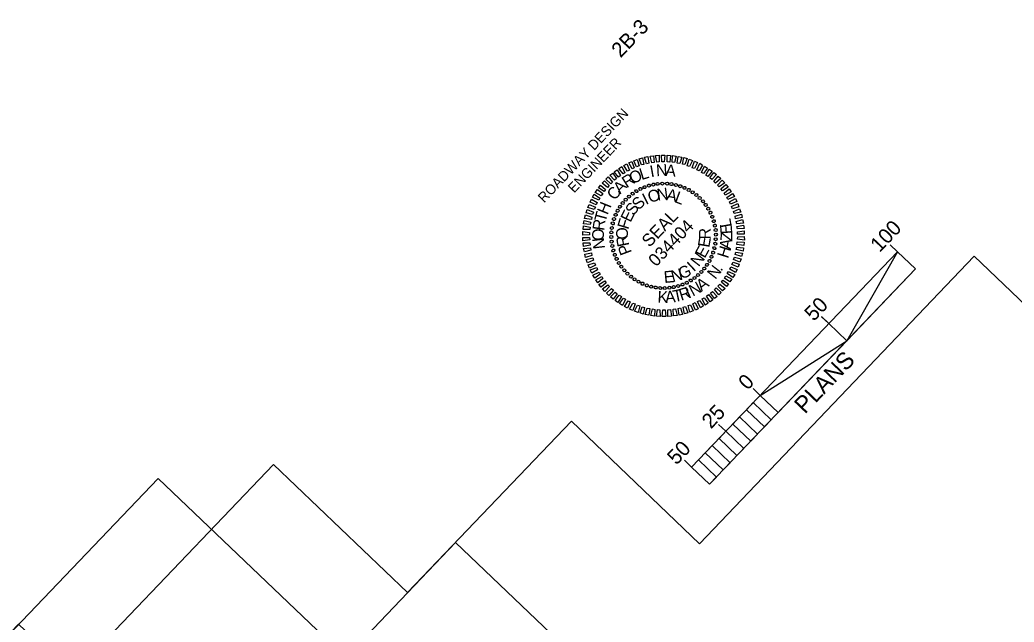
# Model space of a CAD drawing. Extents: x 2326836 to 2328631, y 602012 to 603789.
# Drawn here: x 2327551 to 2328051, y 603486 to 603789 of the extents above; entities that cross this region are included whole.
import ezdxf

# ---------------------------------------------------------------- set-up
doc = ezdxf.new("R2010")
doc.units = 0
for name, color, linetype in [('Scratch_Level_1', 7, 'Continuous'), ('Sheet Data Field CELL', 7, 'Continuous'), ('Sheet Plan CELL', 7, 'Continuous'), ('Sheet Title CELL', 7, 'Continuous')]:
    doc.layers.add(name, color=color, linetype=linetype)

msp = doc.modelspace()

# ---------------------------------------------------------------- linework, layer by layer
at = {"layer": 'Scratch_Level_1'}
msp.add_lwpolyline([(2326885.09, 602788.9), (2327620.52, 603558.61), (2327714.85, 603468.48), (2327770.17, 603526.38), (2328049.95, 603259.07), (2327259.2, 602431.46)], close=True, dxfattribs=at)
at = {"layer": 'Sheet Data Field CELL'}
for p, q in [((2327865.2, 603705.2), (2327865.2, 603705.2)), ((2327867.36, 603705.99), (2327867.36, 603705.99)), ((2327869.6, 603706.49), (2327869.6, 603706.49)), ((2327871.89, 603706.88), (2327871.89, 603706.88)), ((2327874.15, 603707.01), (2327874.15, 603707.01)), ((2327876.49, 603706.99), (2327876.49, 603706.99)), ((2327878.73, 603706.71), (2327878.73, 603706.71)), ((2327881.01, 603706.24), (2327881.01, 603706.24)), ((2327883.23, 603705.63), (2327883.23, 603705.63)), ((2327885.34, 603704.82), (2327885.34, 603704.82)), ((2327857.41, 603700.47), (2327857.41, 603700.47)), ((2327859.21, 603701.88), (2327859.21, 603701.88)), ((2327861.05, 603703.17), (2327861.05, 603703.17)), ((2327863.08, 603704.3), (2327863.08, 603704.3)), ((2327887.38, 603703.79), (2327887.38, 603703.79)), ((2327889.37, 603702.53), (2327889.37, 603702.53)), ((2327891.24, 603701.23), (2327891.24, 603701.23)), ((2327892.97, 603699.71), (2327892.97, 603699.71)), ((2327852.9, 603695.27), (2327852.9, 603695.27)), ((2327854.2, 603697.14), (2327854.2, 603697.14)), ((2327855.73, 603698.88), (2327855.73, 603698.88)), ((2327894.56, 603698.03), (2327894.56, 603698.03)), ((2327895.97, 603696.23), (2327895.97, 603696.23)), ((2327897.27, 603694.38), (2327897.27, 603694.38)), ((2327850.61, 603691.24), (2327850.61, 603691.24)), ((2327851.64, 603693.29), (2327851.64, 603693.29)), ((2327898.39, 603692.35), (2327898.39, 603692.35)), ((2327899.29, 603690.23), (2327899.29, 603690.23)), ((2327848.72, 603684.63), (2327848.72, 603684.63)), ((2327849.19, 603686.92), (2327849.19, 603686.92)), ((2327849.81, 603689.13), (2327849.81, 603689.13)), ((2327900.08, 603688.07), (2327900.08, 603688.07)), ((2327900.58, 603685.83), (2327900.58, 603685.83)), ((2327848.43, 603680.06), (2327848.43, 603680.06)), ((2327848.44, 603682.4), (2327848.44, 603682.4)), ((2327900.97, 603683.54), (2327900.97, 603683.54)), ((2327901.1, 603681.28), (2327901.1, 603681.28)), ((2327848.55, 603677.8), (2327848.55, 603677.8)), ((2327848.94, 603675.51), (2327848.94, 603675.51)), ((2327900.34, 603674.42), (2327900.34, 603674.42)), ((2327900.8, 603676.7), (2327900.8, 603676.7)), ((2327901.08, 603678.94), (2327901.08, 603678.94)), ((2327849.44, 603673.26), (2327849.44, 603673.26)), ((2327850.23, 603671.11), (2327850.23, 603671.11)), ((2327898.91, 603670.09), (2327898.91, 603670.09)), ((2327899.72, 603672.21), (2327899.72, 603672.21)), ((2327851.14, 603668.99), (2327851.14, 603668.99)), ((2327852.26, 603666.95), (2327852.26, 603666.95)), ((2327853.56, 603665.11), (2327853.56, 603665.11)), ((2327896.62, 603666.07), (2327896.62, 603666.07)), ((2327897.88, 603668.05), (2327897.88, 603668.05)), ((2327854.97, 603663.31), (2327854.97, 603663.31)), ((2327856.56, 603661.63), (2327856.56, 603661.63)), ((2327858.29, 603660.11), (2327858.29, 603660.11)), ((2327890.32, 603659.46), (2327890.32, 603659.46)), ((2327892.12, 603660.87), (2327892.12, 603660.87)), ((2327893.8, 603662.46), (2327893.8, 603662.46)), ((2327895.33, 603664.19), (2327895.33, 603664.19)), ((2327860.16, 603658.81), (2327860.16, 603658.81)), ((2327862.14, 603657.55), (2327862.14, 603657.55)), ((2327864.19, 603656.52), (2327864.19, 603656.52)), ((2327866.3, 603655.71), (2327866.3, 603655.71)), ((2327868.51, 603655.1), (2327868.51, 603655.1)), ((2327870.8, 603654.63), (2327870.8, 603654.63)), ((2327873.04, 603654.35), (2327873.04, 603654.35)), ((2327875.38, 603654.33), (2327875.38, 603654.33)), ((2327877.64, 603654.46), (2327877.64, 603654.46)), ((2327879.92, 603654.85), (2327879.92, 603654.85)), ((2327882.17, 603655.35), (2327882.17, 603655.35)), ((2327884.33, 603656.14), (2327884.33, 603656.14)), ((2327886.44, 603657.04), (2327886.44, 603657.04)), ((2327888.48, 603658.16), (2327888.48, 603658.16)), ((2327957.91, 603636.55), (2327954.3, 603640)), ((2327906.11, 603582.32), (2327902.49, 603585.77)), ((2327888.83, 603564.25), (2327885.22, 603567.69))]:
    msp.add_line(p, q, dxfattribs=at)
for points in [[(2327863.75, 603716.32), (2327862.51, 603719.38), (2327864.23, 603719.94), (2327864.89, 603716.62)], [(2327866.18, 603716.86), (2327865.19, 603720.27), (2327866.92, 603720.53), (2327867.42, 603717.28)], [(2327868.79, 603717.37), (2327867.99, 603720.76), (2327869.76, 603720.98), (2327870.01, 603717.61)], [(2327871.34, 603717.73), (2327870.79, 603721.17), (2327872.57, 603721.24), (2327872.59, 603717.93)], [(2327873.97, 603717.88), (2327873.69, 603721.21), (2327875.47, 603721.28), (2327875.12, 603717.89)], [(2327876.6, 603717.95), (2327876.51, 603721.32), (2327878.29, 603721.17), (2327877.87, 603717.78)], [(2327879.18, 603717.72), (2327879.3, 603721.1), (2327881.09, 603720.8), (2327880.34, 603717.5)], [(2327881.68, 603717.26), (2327882.1, 603720.66), (2327883.93, 603720.32), (2327882.95, 603717.09)], [(2327884.3, 603716.7), (2327884.95, 603720.1), (2327886.6, 603719.5), (2327885.46, 603716.48)], [(2327854.39, 603711.82), (2327852.24, 603714.52), (2327853.76, 603715.54), (2327855.33, 603712.45)], [(2327856.6, 603713.21), (2327854.74, 603715.99), (2327856.23, 603716.83), (2327857.61, 603713.77)], [(2327858.89, 603714.3), (2327857.28, 603717.43), (2327858.74, 603718.08), (2327859.98, 603714.94)], [(2327861.23, 603715.36), (2327859.84, 603718.42), (2327861.48, 603719.12), (2327862.43, 603715.82)], [(2327886.67, 603715.94), (2327887.62, 603719.28), (2327889.31, 603718.64), (2327887.88, 603715.54)], [(2327889.13, 603714.96), (2327890.29, 603718.24), (2327891.88, 603717.56), (2327890.29, 603714.6)], [(2327891.55, 603713.87), (2327892.94, 603717.16), (2327894.42, 603716.21), (2327892.6, 603713.39)], [(2327893.82, 603712.62), (2327895.33, 603715.73), (2327896.86, 603714.75), (2327894.85, 603712.11)], [(2327848.24, 603706.86), (2327845.73, 603709.17), (2327846.94, 603710.4), (2327849.13, 603707.75)], [(2327850.13, 603708.68), (2327847.77, 603711.14), (2327849.17, 603712.2), (2327851.14, 603709.46)], [(2327852.15, 603710.24), (2327850, 603712.87), (2327851.37, 603713.96), (2327853.12, 603711.06)], [(2327895.99, 603711.26), (2327897.77, 603714.27), (2327899.19, 603713.17), (2327897.06, 603710.56)], [(2327898.06, 603709.79), (2327900.06, 603712.58), (2327901.45, 603711.45), (2327899.06, 603709.01)], [(2327900.02, 603708.05), (2327902.22, 603710.66), (2327903.53, 603709.45), (2327900.95, 603707.19)], [(2327844.91, 603702.93), (2327842.05, 603704.79), (2327843.1, 603706.24), (2327845.64, 603703.97)], [(2327846.49, 603705.04), (2327843.81, 603707.16), (2327845.02, 603708.4), (2327847.38, 603705.93)], [(2327901.91, 603706.23), (2327904.3, 603708.67), (2327905.51, 603707.41), (2327902.77, 603705.3)], [(2327903.59, 603704.33), (2327906.1, 603706.58), (2327907.26, 603705.22), (2327904.34, 603703.28)], [(2327842.15, 603698.63), (2327838.97, 603700.06), (2327839.91, 603701.62), (2327842.7, 603699.61)], [(2327843.43, 603700.87), (2327840.39, 603702.53), (2327841.45, 603703.91), (2327844.17, 603701.9)], [(2327905.27, 603702.21), (2327907.78, 603704.31), (2327908.85, 603702.83), (2327905.8, 603701.15)], [(2327906.66, 603700), (2327909.37, 603701.93), (2327910.39, 603700.48), (2327907.18, 603698.94)], [(2327907.98, 603697.71), (2327910.88, 603699.46), (2327911.61, 603697.86), (2327908.39, 603696.54)], [(2327839.81, 603693.86), (2327836.65, 603694.92), (2327837.26, 603696.5), (2327840.47, 603695.03)], [(2327840.94, 603696.31), (2327837.81, 603697.56), (2327838.56, 603699.08), (2327841.42, 603697.37)], [(2327908.96, 603695.38), (2327912.05, 603696.95), (2327912.72, 603695.27), (2327909.45, 603694.21)], [(2327838.45, 603688.9), (2327835.06, 603689.39), (2327835.54, 603691.16), (2327838.67, 603690.06)], [(2327839.06, 603691.41), (2327835.76, 603692.17), (2327836.32, 603693.86), (2327839.49, 603692.58)], [(2327910.02, 603692.97), (2327913.01, 603694.28), (2327913.68, 603692.59), (2327910.33, 603691.83)], [(2327910.83, 603690.51), (2327913.98, 603691.6), (2327914.34, 603689.84), (2327910.95, 603689.25)], [(2327837.66, 603683.78), (2327834.28, 603683.83), (2327834.43, 603685.62), (2327837.83, 603684.98)], [(2327837.85, 603686.31), (2327834.57, 603686.7), (2327834.76, 603688.38), (2327838.17, 603687.59)], [(2327911.3, 603687.93), (2327914.53, 603688.8), (2327914.98, 603687.04), (2327911.57, 603686.75)], [(2327911.7, 603685.42), (2327915.05, 603686.04), (2327915.27, 603684.27), (2327911.9, 603684.24)], [(2327837.43, 603681.14), (2327834.17, 603681), (2327834.1, 603682.78), (2327837.57, 603682.37)], [(2327837.6, 603678.62), (2327834.21, 603678.11), (2327834.21, 603679.89), (2327837.56, 603679.8)], [(2327911.92, 603682.72), (2327915.32, 603683.23), (2327915.31, 603681.45), (2327911.97, 603681.54)], [(2327912.1, 603680.2), (2327915.36, 603680.34), (2327915.43, 603678.56), (2327911.96, 603678.97)], [(2327837.82, 603675.92), (2327834.47, 603675.3), (2327834.25, 603677.07), (2327837.63, 603677.1)], [(2327838.22, 603673.41), (2327834.99, 603672.54), (2327834.55, 603674.3), (2327837.95, 603674.59)], [(2327911.67, 603675.03), (2327914.96, 603674.64), (2327914.76, 603672.96), (2327911.35, 603673.75)], [(2327911.87, 603677.56), (2327915.25, 603677.51), (2327915.1, 603675.72), (2327911.69, 603676.36)], [(2327838.7, 603670.83), (2327835.55, 603669.74), (2327835.18, 603671.5), (2327838.57, 603672.09)], [(2327839.5, 603668.37), (2327836.51, 603667.06), (2327835.85, 603668.75), (2327839.2, 603669.51)], [(2327910.47, 603669.93), (2327913.76, 603669.17), (2327913.2, 603667.48), (2327910.03, 603668.76)], [(2327911.07, 603672.44), (2327914.47, 603671.95), (2327913.98, 603670.18), (2327910.86, 603671.28)], [(2327840.56, 603665.96), (2327837.47, 603664.39), (2327836.81, 603666.07), (2327840.07, 603667.13)], [(2327841.55, 603663.63), (2327838.65, 603661.88), (2327837.92, 603663.48), (2327841.13, 603664.8)], [(2327908.59, 603665.03), (2327911.72, 603663.78), (2327910.96, 603662.26), (2327908.11, 603663.97)], [(2327909.71, 603667.48), (2327912.87, 603666.42), (2327912.27, 603664.84), (2327909.05, 603666.31)], [(2327842.87, 603661.34), (2327840.16, 603659.41), (2327839.14, 603660.86), (2327842.34, 603662.4)], [(2327844.26, 603659.13), (2327841.74, 603657.03), (2327840.68, 603658.51), (2327843.73, 603660.19)], [(2327906.1, 603660.47), (2327909.13, 603658.81), (2327908.07, 603657.43), (2327905.36, 603659.44)], [(2327907.38, 603662.71), (2327910.56, 603661.28), (2327909.62, 603659.72), (2327906.82, 603661.72)], [(2327845.94, 603657.01), (2327843.43, 603654.76), (2327842.26, 603656.12), (2327845.19, 603658.06)], [(2327847.61, 603655.11), (2327845.22, 603652.67), (2327844.02, 603653.93), (2327846.76, 603656.04)], [(2327901.29, 603654.48), (2327903.79, 603652.17), (2327902.58, 603650.93), (2327900.39, 603653.59)], [(2327903.03, 603656.3), (2327905.72, 603654.18), (2327904.5, 603652.94), (2327902.14, 603655.41)], [(2327904.62, 603658.41), (2327907.48, 603656.55), (2327906.42, 603655.1), (2327903.88, 603657.37)], [(2327849.5, 603653.29), (2327847.31, 603650.68), (2327845.99, 603651.89), (2327848.58, 603654.15)], [(2327851.47, 603651.55), (2327849.46, 603648.76), (2327848.08, 603649.89), (2327850.47, 603652.33)], [(2327853.53, 603650.08), (2327851.76, 603647.07), (2327850.34, 603648.16), (2327852.46, 603650.78)], [(2327895.14, 603649.52), (2327897.29, 603646.82), (2327895.77, 603645.8), (2327894.2, 603648.89)], [(2327897.38, 603651.1), (2327899.52, 603648.47), (2327898.16, 603647.38), (2327896.41, 603650.28)], [(2327899.39, 603652.66), (2327901.76, 603650.2), (2327900.35, 603649.14), (2327898.38, 603651.88)], [(2327855.7, 603648.71), (2327854.19, 603645.61), (2327852.67, 603646.59), (2327854.68, 603649.23)], [(2327857.98, 603647.47), (2327856.59, 603644.18), (2327855.1, 603645.13), (2327856.92, 603647.95)], [(2327860.4, 603646.38), (2327859.23, 603643.1), (2327857.65, 603643.78), (2327859.23, 603646.74)], [(2327862.85, 603645.4), (2327861.91, 603642.06), (2327860.21, 603642.7), (2327861.65, 603645.8)], [(2327865.22, 603644.64), (2327864.58, 603641.24), (2327862.92, 603641.84), (2327864.06, 603644.86)], [(2327883.35, 603644.48), (2327884.34, 603641.07), (2327882.6, 603640.81), (2327882.1, 603644.06)], [(2327885.78, 603645.02), (2327887.01, 603641.95), (2327885.29, 603641.4), (2327884.64, 603644.72)], [(2327888.3, 603645.98), (2327889.69, 603642.92), (2327888.04, 603642.22), (2327887.09, 603645.52)], [(2327890.63, 603647.04), (2327892.24, 603643.91), (2327890.79, 603643.26), (2327889.54, 603646.4)], [(2327892.93, 603648.13), (2327894.78, 603645.35), (2327893.3, 603644.51), (2327891.91, 603647.57)], [(2327867.84, 603644.08), (2327867.42, 603640.68), (2327865.59, 603641.02), (2327866.57, 603644.25)], [(2327870.35, 603643.62), (2327870.23, 603640.24), (2327868.43, 603640.54), (2327869.19, 603643.84)], [(2327872.92, 603643.39), (2327873.02, 603640.02), (2327871.23, 603640.17), (2327871.65, 603643.56)], [(2327875.55, 603643.46), (2327875.84, 603640.13), (2327874.06, 603640.06), (2327874.4, 603643.45)], [(2327878.18, 603643.6), (2327878.73, 603640.17), (2327876.95, 603640.1), (2327876.93, 603643.41)], [(2327880.73, 603643.97), (2327881.54, 603640.58), (2327879.76, 603640.36), (2327879.52, 603643.73)]]:
    msp.add_lwpolyline(points, close=True, dxfattribs=at)
for centre, major_axis in [((2327863.1, 603704.26), (-0.335, 0.677)), ((2327865.2, 603705.19), (-0.274, 0.704)), ((2327867.37, 603705.93), (-0.212, 0.725)), ((2327869.6, 603706.48), (-0.148, 0.741)), ((2327871.87, 603706.83), (-0.083, 0.751)), ((2327874.16, 603706.98), (-0.017, 0.755)), ((2327876.46, 603706.93), (0.049, 0.754)), ((2327878.74, 603706.68), (0.114, 0.747)), ((2327880.99, 603706.24), (0.179, 0.734)), ((2327883.2, 603705.6), (0.242, 0.716)), ((2327885.34, 603704.77), (0.304, 0.692)), ((2327887.4, 603703.75), (0.363, 0.663)), ((2327855.74, 603698.85), (-0.546, 0.522)), ((2327857.39, 603700.44), (-0.499, 0.568)), ((2327859.18, 603701.88), (-0.447, 0.609)), ((2327861.09, 603703.16), (-0.393, 0.646)), ((2327889.36, 603702.57), (0.419, 0.629)), ((2327891.22, 603701.21), (0.472, 0.59)), ((2327892.94, 603699.7), (0.522, 0.546)), ((2327852.87, 603695.27), (-0.629, 0.419)), ((2327854.22, 603697.12), (-0.59, 0.472)), ((2327894.53, 603698.04), (0.568, 0.499)), ((2327895.97, 603696.25), (0.609, 0.447)), ((2327897.25, 603694.34), (0.646, 0.393)), ((2327849.83, 603689.11), (-0.716, 0.242)), ((2327850.66, 603691.25), (-0.692, 0.304)), ((2327851.68, 603693.31), (-0.663, 0.363)), ((2327898.35, 603692.33), (0.677, 0.335)), ((2327899.28, 603690.23), (0.704, 0.274)), ((2327848.75, 603684.65), (-0.747, 0.114)), ((2327849.19, 603686.9), (-0.734, 0.179)), ((2327900.02, 603688.06), (0.725, 0.212)), ((2327900.57, 603685.83), (0.741, 0.148)), ((2327900.92, 603683.56), (0.751, 0.083)), ((2327848.45, 603680.07), (-0.755, -0.017)), ((2327848.5, 603682.37), (-0.754, 0.049)), ((2327901.02, 603678.97), (0.754, -0.049)), ((2327901.07, 603681.27), (0.755, 0.017)), ((2327848.6, 603677.78), (-0.751, -0.083)), ((2327848.96, 603675.51), (-0.741, -0.148)), ((2327900.33, 603674.44), (0.734, -0.179)), ((2327900.78, 603676.69), (0.747, -0.114)), ((2327849.5, 603673.28), (-0.725, -0.212)), ((2327850.24, 603671.11), (-0.704, -0.274)), ((2327851.17, 603669.01), (-0.677, -0.335)), ((2327898.86, 603670.09), (0.692, -0.304)), ((2327899.69, 603672.23), (0.716, -0.242)), ((2327852.28, 603667), (-0.646, -0.393)), ((2327853.55, 603665.09), (-0.609, -0.447)), ((2327895.3, 603664.22), (0.59, -0.472)), ((2327896.66, 603666.07), (0.629, -0.419)), ((2327897.85, 603668.03), (0.663, -0.363)), ((2327854.99, 603663.3), (-0.568, -0.499)), ((2327856.58, 603661.64), (-0.522, -0.546)), ((2327858.31, 603660.13), (-0.472, -0.59)), ((2327860.16, 603658.77), (-0.419, -0.629)), ((2327890.34, 603659.46), (0.447, -0.609)), ((2327892.13, 603660.9), (0.499, -0.568)), ((2327893.79, 603662.49), (0.546, -0.522)), ((2327862.13, 603657.59), (-0.363, -0.663)), ((2327864.19, 603656.57), (-0.304, -0.692)), ((2327866.33, 603655.74), (-0.242, -0.716)), ((2327868.53, 603655.1), (-0.179, -0.734)), ((2327870.78, 603654.66), (-0.114, -0.747)), ((2327873.07, 603654.41), (-0.049, -0.754)), ((2327875.36, 603654.36), (0.017, -0.755)), ((2327877.65, 603654.51), (0.083, -0.751)), ((2327879.92, 603654.86), (0.148, -0.741)), ((2327882.15, 603655.41), (0.212, -0.725)), ((2327884.32, 603656.15), (0.274, -0.704)), ((2327886.42, 603657.08), (0.335, -0.677)), ((2327888.44, 603658.18), (0.393, -0.646))]:
    msp.add_ellipse(centre, major_axis=major_axis, ratio=0.999708, dxfattribs=at)
at = {"layer": 'Sheet Plan CELL'}
msp.add_lwpolyline([(2326835.98, 602737.58), (2327550.28, 603485.23), (2327577.17, 603459.54), (2327678.48, 603565.59), (2327746, 603501.08), (2327828.41, 603587.34), (2327892.92, 603525.71), (2328031.11, 603670.36), (2328251.83, 603459.46), (2327215.55, 602374.93)], close=True, dxfattribs=at)
at = {"layer": 'Sheet Title CELL'}
for p, q in [((2327992.45, 603672.69), (2327988.84, 603676.14)), ((2327992.45, 603672.69), (2327888.83, 603564.23)), ((2327897.87, 603555.6), (2328001.5, 603664.05)), ((2327957.91, 603636.54), (2327954.3, 603639.98)), ((2327957.91, 603636.54), (2327966.95, 603627.9)), ((2327923.38, 603600.37), (2327919.77, 603603.83)), ((2327913.01, 603589.54), (2327922.05, 603580.9)), ((2327906.11, 603582.3), (2327902.49, 603585.76)), ((2327888.83, 603564.23), (2327885.23, 603567.68)), ((2327885.23, 603567.68), (2327885.23, 603567.68))]:
    msp.add_line(p, q, dxfattribs=at)
for points in [[(2327992.45, 603672.69), (2327966.95, 603627.9), (2328001.5, 603664.05)], [(2327923.38, 603600.37), (2327966.95, 603627.9), (2327932.42, 603591.74)], [(2327916.46, 603593.15), (2327919.92, 603596.77), (2327928.96, 603588.12), (2327925.5, 603584.52)], [(2327909.56, 603585.91), (2327913.01, 603589.54), (2327922.05, 603580.9), (2327918.59, 603577.29)], [(2327902.66, 603578.68), (2327906.11, 603582.3), (2327915.14, 603573.67), (2327911.69, 603570.06)], [(2327895.74, 603571.46), (2327899.2, 603575.07), (2327908.24, 603566.43), (2327904.8, 603562.83)], [(2327888.83, 603564.23), (2327892.29, 603567.85), (2327901.32, 603559.21), (2327897.87, 603555.6)]]:
    msp.add_lwpolyline(points, close=True, dxfattribs=at)

# ---------------------------------------------------------------- texts
at = {"layer": 'Sheet Data Field CELL'}
for s, height, rotation, p in [('2B-3', 7.5, 46.3051, (2327853.18, 603769.95)), ('L', 5.92, 17.5247, (2327863.69, 603708.66)), ('I', 5.92, 10.324, (2327868.42, 603710.08)), ('N', 5.92, 3.1227, (2327871.14, 603710.64)), ('A', 5.92, 355.921, (2327875.52, 603710.81)), ('R', 5.92, 31.9249, (2327856.17, 603704.54)), ('O', 5.92, 24.725, (2327859.13, 603706.59)), ('C', 5.92, 53.5237, (2327850.44, 603698.18)), ('A', 5.92, 46.3241, (2327853.02, 603701.44)), ('N', 5.92, 7.7804, (2327871.79, 603698.33)), ('S', 5.92, 45.2042, (2327862.3, 603693.31)), ('I', 5.92, 26.4934, (2327865.9, 603696.13)), ('O', 5.92, 17.1373, (2327867.86, 603697.17)), ('A', 5.92, 349.0641, (2327875.82, 603698.68)), ('L', 5.92, 339.7047, (2327879.87, 603697.73)), ('H', 5.92, 67.9233, (2327846.58, 603690.9)), ('S', 5.92, 54.5594, (2327859.78, 603690.5)), ('T', 5.92, 75.1236, (2327845.54, 603687.22)), ('F', 5.91, 73.2709, (2327857.01, 603683.56)), ('E', 5.92, 63.9149, (2327858.13, 603687.09)), ('SEAL', 6.294, 46.3038, (2327867.69, 603674.56)), ('L', 5.92, 100.6029, (2327909.15, 603685.38)), ('R', 5.92, 82.3243, (2327844.82, 603683.03)), ('O', 5.92, 91.9851, (2327856.94, 603678.91)), ('034404', 6.296, 46.3038, (2327871.02, 603664.79)), ('E', 5.92, 94.4281, (2327909.41, 603681.7)), ('100', 7.5, 46.307, (2327983.45, 603671.97)), ('O', 5.92, 89.5256, (2327844.75, 603678.16)), ('N', 5.92, 96.7273, (2327845.35, 603674.33)), ('R', 5.92, 101.3435, (2327857.58, 603675.82)), ('E', 5.92, 80.4279, (2327897.77, 603674.5)), ('R', 5.92, 89.7852, (2327898.48, 603678.91)), ('Z', 5.92, 87.8886, (2327909.26, 603677.8)), ('P', 5.92, 110.7027, (2327858.91, 603672.31)), ('E', 5.92, 61.7156, (2327895.5, 603669.03)), ('H', 5.92, 72.679, (2327907.2, 603668.98)), ('A', 5.92, 80.6389, (2327908.57, 603673.53)), ('N', 5.92, 52.3602, (2327892.44, 603664.78)), ('G', 5.92, 24.2941, (2327883.82, 603658.61)), ('I', 5.92, 43.005, (2327889.94, 603662.31)), ('N', 5.92, 51.8992, (2327900.81, 603658.42)), ('E', 5.92, 5.5807, (2327875.16, 603656.89)), ('N', 5.92, 14.9378, (2327879.38, 603657.28)), ('.', 5.92, 60.3198, (2327903.86, 603662.42)), ('R', 5.92, 17.6086, (2327883.57, 603647.94)), ('I', 5.92, 24.0137, (2327887.22, 603649.08)), ('N', 5.92, 28.1345, (2327889.49, 603650.02)), ('A', 5.92, 36.5552, (2327893.89, 603652.45)), ('K', 5.92, 357.4718, (2327871.63, 603647.08)), ('A', 5.92, 4.376, (2327875.75, 603646.9)), ('T', 5.92, 11.6257, (2327880.07, 603647.24)), ('50', 7.5, 46.307, (2327950.35, 603637.3)), ('25', 7.5, 46.307, (2327898.64, 603583.19)), ('50', 7.5, 46.307, (2327881.27, 603565))]:
    msp.add_text(s, height=height, rotation=rotation, dxfattribs=at).set_placement(p)
at = {"layer": 'Sheet Plan CELL'}
for s, height, p in [('ROADWAY DESIGN', 5.0001, (2327814.66, 603697.01)), ('ENGINEER', 5, (2327829.77, 603701.92))]:
    msp.add_text(s, height=height, rotation=46.3032, dxfattribs=at).set_placement(p)
at = {"layer": 'Sheet Title CELL'}
for s, height, p in [('PLANS', 8.5, (2327945.88, 603590.63)), ('0', 7.5, (2327917.03, 603602.63))]:
    msp.add_text(s, height=height, rotation=46.307, dxfattribs=at).set_placement(p)

doc.saveas('drawing.dxf')
